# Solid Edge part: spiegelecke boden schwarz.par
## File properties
Author: Dieter
Template: Normal.par
Last saved by: Dieter
Revision: 2
Application: Solid Edge
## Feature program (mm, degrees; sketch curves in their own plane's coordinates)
sketch for "unnamed Protrusion 1" plane through (0, 0, 0) normal (0, 0, 1) x-axis (1, 0, 0)
  line (-250, -250) -> (250, -250)
  line (250, -250) -> (250, 250)
  line (250, 250) -> (-250, 250)
  line (-250, 250) -> (-250, -250)
extrude "unnamed Protrusion 1" add finite 2 along +normal
sketch for "unnamed Protrusion 2" plane through (0, 0, 2) normal (0, 0, 1) x-axis (1, 0, 0)
  line (-250, -250) -> (-225.2903, 60.3871)
  line (-225.2903, 60.3871) -> (-83.6129, 197.4194)
  line (-83.6129, 197.4194) -> (250, 250)
  line (250, 250) -> (250, 237.2853)
  line (250, 237.2853) -> (-83.6129, 184.3775)
  line (-83.6129, 184.3775) -> (-216.7574, 51.0984)
  line (-216.7574, 51.0984) -> (-237.6452, -250)
  line (-237.6452, -250) -> (-250, -250)
extrude "unnamed Protrusion 2" add finite 300 along +normal
sketch for "unnamed Cutout 1" plane through (6.1774, -6.3573, 2) normal (0, 0, 1) x-axis (1, 0, 0)
  line (-256.1774, -243.6427) -> (-231.4677, 66.7444)
  line (-231.4677, 66.7444) -> (-89.7903, 203.7767)
  line (-89.7903, 203.7767) -> (243.8226, 256.3573)
  line (243.8226, 256.3573) -> (-256.1774, 256.3573)
  line (-256.1774, 256.3573) -> (-256.1774, -243.6427)
extrude "unnamed Cutout 1" cut finite 603.25 symmetric
sketch for "unnamed Cutout 2" plane through (6.1774, -6.3573, 2) normal (0, 0, 1) x-axis (1, 0, 0)
extrude "unnamed Cutout 2" cut finite 247.65 symmetric
